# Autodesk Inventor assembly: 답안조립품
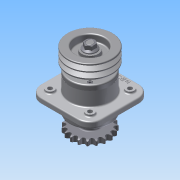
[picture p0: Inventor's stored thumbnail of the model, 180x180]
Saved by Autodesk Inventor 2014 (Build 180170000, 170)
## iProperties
Created: 2015-09
Part Number: 답안조립품
Document SubType Name: Assembly
Designer: study
Author: study
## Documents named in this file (12)
- C:\Users\study\Desktop\450909V1017\답안조립품.iam
- C:\Users\study\Desktop\450909V1017\1-본체.ipt
- C:\Users\study\Desktop\450909V1017\6-베어링 6206.ipt
- C:\Users\study\Desktop\450909V1017\2-커버.ipt
- C:\Users\study\Desktop\450909V1017\8-오일실 30x42.ipt
- C:\Users\study\Desktop\450909V1017\3-축.ipt
- C:\Users\study\Desktop\450909V1017\11-키 6x6.ipt
- C:\Users\study\Desktop\450909V1017\10-M6.ipt
- C:\Users\study\Desktop\450909V1017\5-체인 스프로킷.ipt
- C:\Users\study\Desktop\450909V1017\4-V벨트풀리.ipt
- C:\Users\study\Desktop\450909V1017\9-M16-너트.ipt
- C:\Users\study\Desktop\450909V1017\7-부시.ipt
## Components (23 placed, 11 different names)
1. 1-본체:1
2. 6-베어링 6206:1
3. 6-베어링 6206:2
4. 2-커버:1
5. 8-8-오일실 30x42:1
6. 2-커버:2
7. 8-8-오일실 30x42:2
8. 3-축:1 — 각도:1, 각도:2
9. 11-키 6x6:1 — 각도:1, 각도:4
10. 11-키 6x6:2 — 각도:2, 각도:3
11. 5-체인 스프로킷:1 — 각도:3
12. 4-V벨트풀리:1 — 각도:4
13. 9-M16 너트:1
14. 9-M16 너트:2
15. 7-부시:1
16. 10-M6:1
17. 10-M6:3
18. 10-M6:4
19. 10-M6:5
20. 10-M6:2
21. 10-M6:6
22. 10-M6:7
23. 10-M6:8
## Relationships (4: Angle 4)
- 각도:1 [Angle]: 3-축:1 ↔ 11-키 6x6:1
- 각도:2 [Angle]: 3-축:1 ↔ 11-키 6x6:2
- 각도:3 [Angle]: 11-키 6x6:2 ↔ 5-체인 스프로킷:1
- 각도:4 [Angle]: 11-키 6x6:1 ↔ 4-V벨트풀리:1
